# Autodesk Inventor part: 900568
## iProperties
Created: 2007-12
Part Number: 900568
Document SubType Name: Modeling
Designer: CF
Density: 1.06 g/cm^3
Categories: <MemberInstance><Categories><Category DisplayName="" Mnemonic="CABLEANDHARNESS" InternalName="e4a7e005-5e42-4d16-b293-125e7f0d0512"><Category DisplayName="" Mne
Mass: 5.15771 g
Surface Area: 57.5307 cm^2
Volume: 4.86577 cm^3
Material: ABS Plastic
Description: S65 CONTROL SWITCH CONNECTOR
GlobalPropertyList: <PropertyList/>
Component Category: Electrical
Author: CF
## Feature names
1. Extrusion1
2. Extrusion2
3. Extrusion3
4. Rectangular Pattern1
5. Chamfer1
6. Extrusion4
7. Extrusion5
8. Extrusion6
9. Mirror1
10. Chamfer2
11. Revolution1
12. Rectangular Pattern2
